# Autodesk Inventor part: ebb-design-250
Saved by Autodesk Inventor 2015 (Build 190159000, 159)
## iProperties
Created: 2020-07
Part Number: ebb-design-250
Checked By: TraceParts S.A.
Material: Generic
Catalog Web Link: www.traceparts.com
Document SubType Name: Modeling
Designer: TraceParts
Density: 1 g/cm^3
Appearance: Default
Company: TraceParts S.A.
Author: TraceParts
REFERENCE: EBB-DESIGN-250
DESIGN: EBB-DESIGN-250
SUPPLIER: Soler & Palau
TraceParts.PartNumber: 10-04022019-080829
TraceParts.PartTitle: EBB-DESIGN
TraceParts.InstanceId: 10-04022019-080829EKMT2YRI4C087I2LGC6PPXX3R
TraceParts.PartStatus: Published
TraceParts.PartVersion: 1.0.1
TRACEPARTS: TRACEPARTS
TraceParts.PartLanguage: en
TraceParts.ClassPath: SOLER_PALAU:10-04022019-080829
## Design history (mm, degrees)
feature "ebb-design-250"
body "Solid1"
